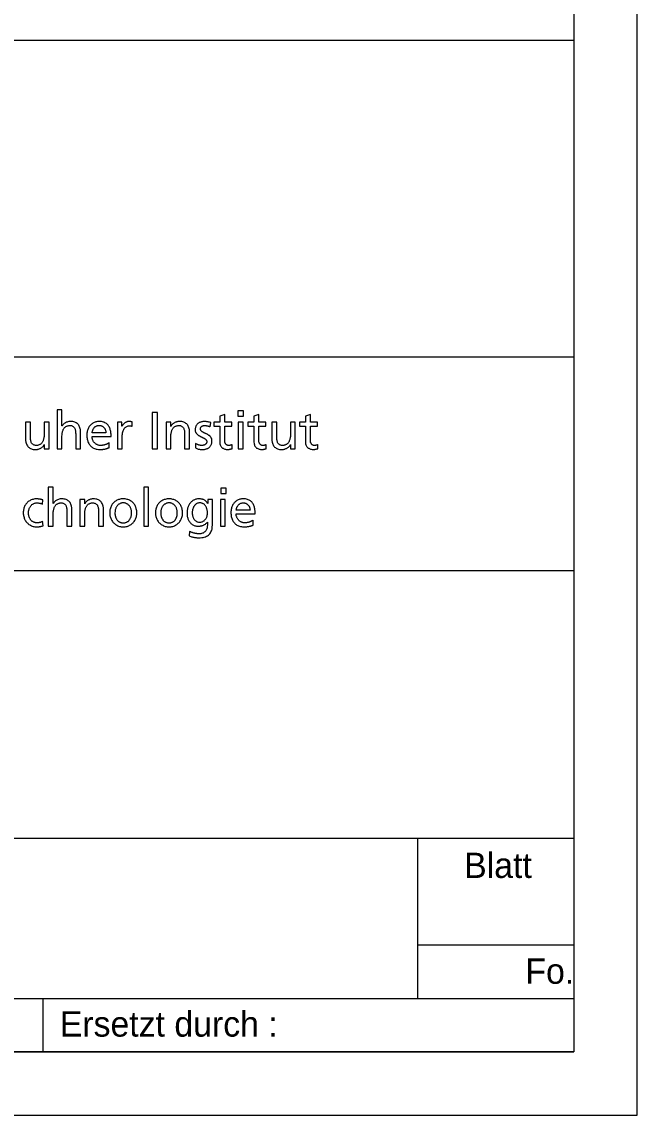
# Model space of a CAD drawing. Extents: x 0 to 168, y 0 to 119.
# Drawn here: x 158.47 to 168.2, y 0 to 17.3 of the extents above; entities that cross this region are included whole.
import ezdxf

# ---------------------------------------------------------------- set-up
doc = ezdxf.new("R2010")
doc.units = 0
doc.layers.add('90_Plankopf', color=7, linetype='Continuous')

msp = doc.modelspace()

# ---------------------------------------------------------------- linework, layer by layer
at = {"layer": '90_Plankopf'}
for p, q in [((167.2, 16.998), (131.624, 16.998)), ((167.2, 16.998), (167.2, 1)), ((131.624, 11.998), (167.2, 11.998)), ((131.624, 11.998), (167.2, 11.998)), ((167.2, 11.998), (167.2, 1)), ((160.211, 10.897), (160.211, 10.966)), ((161.446, 10.888), (161.453, 10.956)), ((159.794, 10.792), (159.577, 10.792)), ((159.577, 10.734), (159.877, 10.734)), ((159.845, 10.559), (159.845, 10.636)), ((161.214, 10.624), (161.21, 10.554)), ((161.792, 10.543), (161.792, 10.609)), ((162.333, 10.543), (162.333, 10.609)), ((163.149, 10.543), (163.149, 10.609)), ((158.79, 9.667), (158.797, 9.732)), ((162.075, 9.568), (161.857, 9.568)), ((158.8, 9.325), (158.794, 9.394)), ((161.857, 9.51), (162.157, 9.51)), ((162.125, 9.335), (162.125, 9.412)), ((161.119, 9.235), (161.111, 9.163)), ((150.4, 8.614), (167.2, 8.614)), ((150.4, 4.384), (167.2, 4.384)), ((164.729, 1.846), (164.729, 4.384)), ((164.729, 2.692), (167.2, 2.692)), ((150.4, 1.846), (167.2, 1.846)), ((158.8, 1), (158.8, 1.846)), ((167.2, 1), (131.624, 1)), ((133.96, 1), (167.2, 1)), ((133.96, 1), (167.2, 1))]:
    msp.add_line(p, q, dxfattribs=at)
for points in [[(0, 0), (168.2, 0), (168.2, 118.8), (0, 118.8)], [(5, 117.8), (167.2, 117.8), (167.2, 1), (5, 1)]]:
    msp.add_lwpolyline(points, close=True, dxfattribs=at)
for points in [[(159.102, 10.902), (159.1, 10.902), (159.1, 11.16), (159.023, 11.16), (159.023, 10.541), (159.1, 10.541), (159.1, 10.736)], [(160.529, 10.541), (160.612, 10.541), (160.612, 11.117), (160.529, 11.117), (160.529, 10.541)], [(161.674, 10.669), (161.674, 10.899), (161.786, 10.899), (161.786, 10.962), (161.674, 10.962), (161.674, 11.084), (161.597, 11.059), (161.597, 10.962), (161.502, 10.962), (161.502, 10.899), (161.597, 10.899), (161.597, 10.653)], [(161.971, 11.056), (161.971, 11.144), (161.883, 11.144), (161.883, 11.056), (161.971, 11.056)], [(162.215, 10.669), (162.215, 10.899), (162.327, 10.899), (162.327, 10.962), (162.215, 10.962), (162.215, 11.084), (162.138, 11.059), (162.138, 10.962), (162.043, 10.962), (162.043, 10.899), (162.138, 10.899), (162.138, 10.653)], [(163.031, 10.669), (163.031, 10.899), (163.142, 10.899), (163.142, 10.962), (163.031, 10.962), (163.031, 11.084), (162.953, 11.059), (162.953, 10.962), (162.858, 10.962), (162.858, 10.899), (162.953, 10.899), (162.953, 10.653)], [(158.601, 10.744), (158.601, 10.962), (158.523, 10.962), (158.523, 10.712)], [(158.819, 10.608), (158.82, 10.608), (158.82, 10.541), (158.895, 10.541), (158.895, 10.962), (158.818, 10.962), (158.818, 10.767)], [(160.05, 10.897), (160.049, 10.897), (160.049, 10.962), (159.976, 10.962), (159.976, 10.541), (160.054, 10.541), (160.054, 10.733)], [(160.823, 10.895), (160.822, 10.895), (160.822, 10.962), (160.746, 10.962), (160.746, 10.541), (160.824, 10.541), (160.824, 10.736)], [(161.888, 10.962), (161.888, 10.541), (161.966, 10.541), (161.966, 10.962), (161.888, 10.962)], [(162.497, 10.744), (162.497, 10.962), (162.419, 10.962), (162.419, 10.712)], [(162.715, 10.608), (162.716, 10.608), (162.716, 10.541), (162.791, 10.541), (162.791, 10.962), (162.714, 10.962), (162.714, 10.767)], [(159.317, 10.759), (159.317, 10.541), (159.395, 10.541), (159.395, 10.791)], [(161.041, 10.759), (161.041, 10.541), (161.119, 10.541), (161.119, 10.791)], [(158.964, 9.678), (158.962, 9.678), (158.962, 9.936), (158.884, 9.936), (158.884, 9.317), (158.962, 9.317), (158.962, 9.512)], [(160.393, 9.317), (160.47, 9.317), (160.47, 9.936), (160.393, 9.936), (160.393, 9.317)], [(161.699, 9.832), (161.699, 9.92), (161.611, 9.92), (161.611, 9.832), (161.699, 9.832)], [(159.461, 9.671), (159.459, 9.671), (159.459, 9.738), (159.384, 9.738), (159.384, 9.317), (159.461, 9.317), (159.461, 9.512)], [(161.479, 9.335), (161.479, 9.738), (161.407, 9.738), (161.407, 9.676), (161.406, 9.676)], [(161.606, 9.738), (161.606, 9.317), (161.684, 9.317), (161.684, 9.738), (161.606, 9.738)], [(159.179, 9.535), (159.179, 9.317), (159.257, 9.317), (159.257, 9.567)], [(159.679, 9.535), (159.679, 9.317), (159.756, 9.317), (159.756, 9.567)], [(161.4, 9.382), (161.401, 9.382), (161.401, 9.341)]]:
    msp.add_lwpolyline(points, dxfattribs=at)
for points in [[(159.1, 10.736), (159.1, 10.762), (159.103, 10.785), (159.108, 10.806), (159.113, 10.827), (159.121, 10.846), (159.131, 10.861), (159.142, 10.876), (159.155, 10.888), (159.171, 10.897), (159.187, 10.905), (159.206, 10.909), (159.228, 10.909), (159.251, 10.908), (159.268, 10.902), (159.281, 10.89), (159.295, 10.879), (159.304, 10.862), (159.309, 10.841), (159.315, 10.819), (159.317, 10.792), (159.317, 10.759)], [(159.395, 10.791), (159.395, 10.829), (159.389, 10.861), (159.378, 10.888), (159.367, 10.915), (159.35, 10.936), (159.327, 10.95), (159.303, 10.965), (159.274, 10.972), (159.237, 10.972), (159.208, 10.972), (159.181, 10.966), (159.158, 10.954), (159.135, 10.942), (159.116, 10.924), (159.102, 10.902)], [(159.877, 10.734), (159.877, 10.768), (159.874, 10.8), (159.868, 10.829), (159.861, 10.857), (159.851, 10.882), (159.837, 10.904), (159.822, 10.925), (159.803, 10.942), (159.78, 10.954), (159.756, 10.966), (159.726, 10.972), (159.691, 10.972), (159.661, 10.972), (159.635, 10.967), (159.61, 10.956), (159.586, 10.946), (159.565, 10.931), (159.548, 10.912), (159.531, 10.893), (159.517, 10.871), (159.508, 10.845), (159.499, 10.819), (159.494, 10.79), (159.494, 10.759), (159.494, 10.725), (159.498, 10.694), (159.507, 10.666), (159.516, 10.638), (159.529, 10.614), (159.547, 10.594), (159.565, 10.574), (159.587, 10.558), (159.615, 10.548), (159.642, 10.537), (159.675, 10.531), (159.712, 10.531), (159.735, 10.531), (159.754, 10.533), (159.771, 10.536), (159.787, 10.539), (159.801, 10.543), (159.813, 10.547), (159.824, 10.551), (159.835, 10.555), (159.845, 10.559)], [(159.577, 10.792), (159.578, 10.806), (159.581, 10.82), (159.586, 10.833), (159.591, 10.847), (159.598, 10.86), (159.607, 10.871), (159.616, 10.883), (159.627, 10.892), (159.641, 10.899), (159.654, 10.906), (159.671, 10.909), (159.69, 10.909), (159.706, 10.909), (159.721, 10.906), (159.734, 10.9), (159.747, 10.894), (159.758, 10.886), (159.767, 10.875), (159.776, 10.864), (159.783, 10.852), (159.787, 10.838), (159.792, 10.823), (159.794, 10.808), (159.794, 10.792)], [(160.211, 10.966), (160.206, 10.967), (160.201, 10.968), (160.196, 10.969), (160.191, 10.97), (160.186, 10.971), (160.18, 10.971), (160.174, 10.972), (160.168, 10.972), (160.16, 10.972), (160.145, 10.972), (160.131, 10.969), (160.116, 10.962), (160.102, 10.956), (160.09, 10.947), (160.078, 10.936), (160.067, 10.925), (160.057, 10.912), (160.05, 10.897)], [(160.054, 10.733), (160.054, 10.768), (160.059, 10.799), (160.068, 10.824), (160.078, 10.85), (160.091, 10.87), (160.108, 10.883), (160.125, 10.897), (160.145, 10.904), (160.168, 10.904), (160.175, 10.904), (160.182, 10.904), (160.19, 10.903), (160.197, 10.902), (160.204, 10.9), (160.211, 10.897)], [(161.119, 10.791), (161.119, 10.829), (161.113, 10.861), (161.102, 10.888), (161.091, 10.915), (161.074, 10.936), (161.05, 10.95), (161.027, 10.965), (160.997, 10.972), (160.961, 10.972), (160.941, 10.972), (160.922, 10.969), (160.904, 10.963), (160.886, 10.957), (160.87, 10.948), (160.856, 10.936), (160.842, 10.925), (160.831, 10.911), (160.823, 10.895)], [(160.824, 10.736), (160.824, 10.762), (160.826, 10.785), (160.832, 10.806), (160.837, 10.827), (160.844, 10.846), (160.855, 10.861), (160.865, 10.876), (160.879, 10.888), (160.895, 10.897), (160.911, 10.905), (160.93, 10.909), (160.952, 10.909), (160.974, 10.908), (160.992, 10.902), (161.005, 10.89), (161.018, 10.879), (161.027, 10.862), (161.033, 10.841), (161.039, 10.819), (161.041, 10.792), (161.041, 10.759)], [(161.453, 10.956), (161.438, 10.96), (161.422, 10.964), (161.407, 10.967), (161.391, 10.97), (161.374, 10.972), (161.356, 10.972), (161.336, 10.972), (161.316, 10.969), (161.298, 10.964), (161.28, 10.959), (161.264, 10.951), (161.251, 10.94), (161.237, 10.929), (161.227, 10.916), (161.219, 10.9), (161.212, 10.883), (161.208, 10.864), (161.208, 10.842), (161.208, 10.826), (161.211, 10.811), (161.218, 10.799), (161.225, 10.787), (161.233, 10.776), (161.244, 10.767), (161.255, 10.758), (161.267, 10.75), (161.28, 10.743), (161.293, 10.736), (161.306, 10.729), (161.319, 10.723), (161.331, 10.717), (161.343, 10.711), (161.354, 10.704), (161.365, 10.698), (161.374, 10.691), (161.38, 10.683), (161.387, 10.675), (161.39, 10.665), (161.39, 10.654), (161.39, 10.643), (161.388, 10.633), (161.383, 10.626), (161.378, 10.618), (161.372, 10.612), (161.364, 10.607), (161.356, 10.602), (161.348, 10.599), (161.338, 10.597), (161.329, 10.595), (161.32, 10.594), (161.311, 10.594), (161.303, 10.594), (161.294, 10.595), (161.283, 10.597), (161.272, 10.599), (161.26, 10.603), (161.248, 10.607), (161.236, 10.612), (161.225, 10.617), (161.214, 10.624)], [(161.21, 10.554), (161.228, 10.545), (161.247, 10.539), (161.267, 10.536), (161.286, 10.532), (161.306, 10.531), (161.326, 10.531), (161.345, 10.531), (161.363, 10.534), (161.38, 10.539), (161.398, 10.544), (161.414, 10.552), (161.428, 10.563), (161.441, 10.574), (161.452, 10.588), (161.46, 10.604), (161.469, 10.621), (161.473, 10.64), (161.473, 10.662), (161.473, 10.682), (161.469, 10.698), (161.463, 10.711), (161.456, 10.724), (161.447, 10.736), (161.437, 10.745), (161.426, 10.754), (161.414, 10.762), (161.401, 10.769), (161.388, 10.776), (161.375, 10.782), (161.362, 10.787), (161.349, 10.793), (161.337, 10.799), (161.327, 10.805), (161.316, 10.812), (161.307, 10.819), (161.3, 10.827), (161.294, 10.836), (161.291, 10.846), (161.29, 10.858), (161.291, 10.87), (161.294, 10.879), (161.301, 10.887), (161.308, 10.894), (161.317, 10.9), (161.328, 10.904), (161.339, 10.908), (161.351, 10.909), (161.365, 10.909), (161.369, 10.909), (161.375, 10.909), (161.383, 10.908), (161.39, 10.906), (161.398, 10.905), (161.406, 10.903), (161.414, 10.901), (161.422, 10.898), (161.429, 10.896), (161.436, 10.893), (161.442, 10.891), (161.446, 10.888)], [(158.818, 10.767), (158.818, 10.742), (158.815, 10.718), (158.81, 10.697), (158.805, 10.676), (158.798, 10.658), (158.787, 10.642), (158.777, 10.627), (158.763, 10.615), (158.747, 10.607), (158.731, 10.598), (158.712, 10.594), (158.69, 10.594), (158.668, 10.595), (158.65, 10.602), (158.637, 10.613), (158.624, 10.624), (158.614, 10.641), (158.609, 10.662), (158.603, 10.684), (158.601, 10.711), (158.601, 10.744)], [(159.845, 10.636), (159.84, 10.632), (159.833, 10.628), (159.824, 10.623), (159.815, 10.618), (159.804, 10.614), (159.792, 10.609), (159.78, 10.605), (159.768, 10.601), (159.754, 10.598), (159.741, 10.596), (159.728, 10.594), (159.715, 10.594), (159.697, 10.594), (159.679, 10.597), (159.663, 10.604), (159.646, 10.611), (159.631, 10.621), (159.618, 10.633), (159.605, 10.645), (159.595, 10.66), (159.588, 10.677), (159.581, 10.694), (159.577, 10.713), (159.577, 10.734)], [(162.714, 10.767), (162.714, 10.742), (162.711, 10.718), (162.706, 10.697), (162.701, 10.676), (162.693, 10.658), (162.683, 10.642), (162.672, 10.627), (162.659, 10.615), (162.643, 10.607), (162.627, 10.598), (162.608, 10.594), (162.586, 10.594), (162.563, 10.595), (162.546, 10.602), (162.533, 10.613), (162.519, 10.624), (162.51, 10.641), (162.505, 10.662), (162.499, 10.684), (162.497, 10.711), (162.497, 10.744)], [(158.523, 10.712), (158.523, 10.674), (158.529, 10.642), (158.54, 10.615), (158.551, 10.588), (158.568, 10.567), (158.592, 10.553), (158.615, 10.539), (158.645, 10.531), (158.681, 10.531), (158.701, 10.531), (158.72, 10.534), (158.738, 10.54), (158.756, 10.547), (158.772, 10.555), (158.786, 10.567), (158.8, 10.578), (158.811, 10.592), (158.819, 10.608)], [(161.597, 10.653), (161.597, 10.625), (161.602, 10.602), (161.613, 10.584), (161.623, 10.566), (161.638, 10.553), (161.657, 10.544), (161.677, 10.536), (161.699, 10.531), (161.726, 10.531), (161.739, 10.531), (161.751, 10.533), (161.762, 10.535), (161.773, 10.538), (161.784, 10.54), (161.792, 10.543)], [(161.792, 10.609), (161.787, 10.605), (161.779, 10.602), (161.771, 10.599), (161.762, 10.596), (161.751, 10.594), (161.74, 10.594), (161.728, 10.594), (161.717, 10.597), (161.707, 10.603), (161.697, 10.608), (161.689, 10.617), (161.683, 10.628), (161.677, 10.639), (161.674, 10.653), (161.674, 10.669)], [(162.138, 10.653), (162.138, 10.625), (162.143, 10.602), (162.153, 10.584), (162.164, 10.566), (162.179, 10.553), (162.198, 10.544), (162.217, 10.536), (162.24, 10.531), (162.267, 10.531), (162.28, 10.531), (162.292, 10.533), (162.303, 10.535), (162.314, 10.538), (162.324, 10.54), (162.333, 10.543)], [(162.333, 10.609), (162.327, 10.605), (162.32, 10.602), (162.311, 10.599), (162.303, 10.596), (162.292, 10.594), (162.28, 10.594), (162.268, 10.594), (162.257, 10.597), (162.248, 10.603), (162.238, 10.608), (162.23, 10.617), (162.224, 10.628), (162.218, 10.639), (162.215, 10.653), (162.215, 10.669)], [(162.419, 10.712), (162.419, 10.674), (162.425, 10.642), (162.436, 10.615), (162.447, 10.588), (162.464, 10.567), (162.487, 10.553), (162.511, 10.539), (162.54, 10.531), (162.577, 10.531), (162.596, 10.531), (162.615, 10.534), (162.633, 10.54), (162.651, 10.547), (162.667, 10.555), (162.682, 10.567), (162.696, 10.578), (162.707, 10.592), (162.715, 10.608)], [(162.953, 10.653), (162.953, 10.625), (162.959, 10.602), (162.969, 10.584), (162.979, 10.566), (162.994, 10.553), (163.014, 10.544), (163.033, 10.536), (163.056, 10.531), (163.083, 10.531), (163.095, 10.531), (163.107, 10.533), (163.118, 10.535), (163.13, 10.538), (163.14, 10.54), (163.149, 10.543)], [(163.149, 10.609), (163.143, 10.605), (163.136, 10.602), (163.127, 10.599), (163.118, 10.596), (163.108, 10.594), (163.096, 10.594), (163.084, 10.594), (163.073, 10.597), (163.063, 10.603), (163.053, 10.608), (163.046, 10.617), (163.04, 10.628), (163.034, 10.639), (163.031, 10.653), (163.031, 10.669)], [(158.797, 9.732), (158.789, 9.735), (158.78, 9.737), (158.77, 9.74), (158.759, 9.742), (158.748, 9.744), (158.736, 9.746), (158.724, 9.747), (158.713, 9.748), (158.703, 9.748), (158.67, 9.748), (158.641, 9.742), (158.615, 9.732), (158.589, 9.721), (158.566, 9.706), (158.547, 9.686), (158.528, 9.666), (158.514, 9.643), (158.504, 9.616), (158.493, 9.589), (158.488, 9.56), (158.488, 9.528), (158.488, 9.498), (158.494, 9.469), (158.504, 9.442), (158.514, 9.416), (158.529, 9.393), (158.548, 9.372), (158.567, 9.352), (158.589, 9.336), (158.616, 9.325), (158.642, 9.313), (158.671, 9.308), (158.703, 9.307), (158.712, 9.307), (158.722, 9.308), (158.733, 9.309), (158.744, 9.309), (158.755, 9.311), (158.767, 9.314), (158.778, 9.316), (158.789, 9.32), (158.8, 9.325)], [(158.794, 9.394), (158.786, 9.389), (158.777, 9.384), (158.768, 9.381), (158.759, 9.377), (158.749, 9.375), (158.739, 9.373), (158.729, 9.371), (158.72, 9.37), (158.711, 9.37), (158.691, 9.37), (158.673, 9.373), (158.658, 9.379), (158.643, 9.385), (158.63, 9.393), (158.618, 9.404), (158.607, 9.414), (158.598, 9.426), (158.591, 9.44), (158.584, 9.453), (158.579, 9.467), (158.576, 9.482), (158.572, 9.498), (158.571, 9.513), (158.571, 9.528), (158.571, 9.548), (158.574, 9.568), (158.58, 9.586), (158.586, 9.605), (158.594, 9.622), (158.606, 9.637), (158.617, 9.652), (158.631, 9.663), (158.648, 9.672), (158.665, 9.681), (158.684, 9.685), (158.706, 9.685), (158.719, 9.685), (158.732, 9.684), (158.746, 9.681), (158.761, 9.678), (158.775, 9.673), (158.79, 9.667)], [(158.962, 9.512), (158.962, 9.538), (158.965, 9.561), (158.97, 9.582), (158.975, 9.604), (158.982, 9.622), (158.993, 9.637), (159.003, 9.653), (159.017, 9.664), (159.033, 9.673), (159.049, 9.681), (159.068, 9.685), (159.09, 9.685), (159.112, 9.684), (159.13, 9.678), (159.143, 9.666), (159.156, 9.655), (159.165, 9.639), (159.171, 9.617), (159.177, 9.595), (159.179, 9.568), (159.179, 9.535)], [(159.257, 9.567), (159.257, 9.605), (159.251, 9.638), (159.24, 9.665), (159.229, 9.691), (159.212, 9.712), (159.188, 9.726), (159.165, 9.741), (159.135, 9.748), (159.099, 9.748), (159.069, 9.748), (159.043, 9.742), (159.02, 9.73), (158.997, 9.718), (158.978, 9.7), (158.964, 9.678)], [(159.756, 9.567), (159.756, 9.605), (159.751, 9.638), (159.739, 9.665), (159.728, 9.691), (159.711, 9.712), (159.688, 9.726), (159.665, 9.741), (159.635, 9.748), (159.598, 9.748), (159.579, 9.748), (159.56, 9.745), (159.542, 9.739), (159.524, 9.733), (159.508, 9.724), (159.494, 9.712), (159.48, 9.701), (159.468, 9.687), (159.461, 9.671)], [(159.461, 9.512), (159.461, 9.538), (159.464, 9.561), (159.469, 9.582), (159.474, 9.604), (159.482, 9.622), (159.492, 9.637), (159.503, 9.653), (159.516, 9.664), (159.532, 9.673), (159.548, 9.681), (159.567, 9.685), (159.589, 9.685), (159.612, 9.684), (159.63, 9.678), (159.643, 9.666), (159.656, 9.655), (159.665, 9.639), (159.67, 9.617), (159.676, 9.595), (159.679, 9.568), (159.679, 9.535)], [(160.279, 9.578), (160.276, 9.591), (160.273, 9.604), (160.268, 9.616), (160.258, 9.643), (160.244, 9.666), (160.225, 9.686), (160.206, 9.706), (160.183, 9.721), (160.157, 9.732), (160.131, 9.742), (160.102, 9.748), (160.07, 9.748), (160.038, 9.748), (160.008, 9.742), (159.982, 9.732), (159.956, 9.721), (159.933, 9.706), (159.914, 9.686), (159.895, 9.666), (159.881, 9.643), (159.871, 9.616), (159.86, 9.589), (159.855, 9.56), (159.855, 9.528)], [(159.938, 9.528), (159.938, 9.548), (159.941, 9.568), (159.947, 9.586), (159.953, 9.605), (159.961, 9.622), (159.973, 9.637), (159.984, 9.652), (159.998, 9.663), (160.014, 9.672), (160.03, 9.681), (160.049, 9.685), (160.07, 9.685), (160.09, 9.685), (160.109, 9.681), (160.125, 9.672), (160.141, 9.663), (160.155, 9.652), (160.166, 9.637), (160.178, 9.622), (160.186, 9.605), (160.192, 9.586), (160.198, 9.568), (160.201, 9.548), (160.201, 9.528), (160.201, 9.513), (160.199, 9.498), (160.196, 9.482), (160.193, 9.467), (160.188, 9.453), (160.181, 9.44), (160.174, 9.426), (160.166, 9.414), (160.155, 9.404), (160.145, 9.393), (160.133, 9.385), (160.118, 9.379), (160.104, 9.373), (160.088, 9.37), (160.07, 9.37), (160.052, 9.37), (160.035, 9.373), (160.021, 9.379), (160.007, 9.385), (159.994, 9.393), (159.984, 9.404), (159.973, 9.414), (159.965, 9.426), (159.958, 9.44), (159.951, 9.453), (159.946, 9.467), (159.943, 9.482), (159.939, 9.498), (159.938, 9.513), (159.938, 9.528)], [(161.003, 9.578), (161, 9.591), (160.997, 9.604), (160.992, 9.616), (160.982, 9.643), (160.968, 9.666), (160.949, 9.686), (160.93, 9.706), (160.907, 9.721), (160.881, 9.732), (160.855, 9.742), (160.826, 9.748), (160.794, 9.748), (160.762, 9.748), (160.732, 9.742), (160.706, 9.732), (160.68, 9.721), (160.657, 9.706), (160.638, 9.686), (160.619, 9.666), (160.605, 9.643), (160.595, 9.616), (160.585, 9.589), (160.579, 9.56), (160.579, 9.528)], [(160.662, 9.528), (160.662, 9.548), (160.665, 9.568), (160.671, 9.586), (160.677, 9.605), (160.685, 9.622), (160.697, 9.637), (160.708, 9.652), (160.722, 9.663), (160.738, 9.672), (160.754, 9.681), (160.773, 9.685), (160.794, 9.685), (160.815, 9.685), (160.833, 9.681), (160.849, 9.672), (160.865, 9.663), (160.879, 9.652), (160.89, 9.637), (160.902, 9.622), (160.91, 9.605), (160.916, 9.586), (160.922, 9.568), (160.925, 9.548), (160.925, 9.528), (160.925, 9.513), (160.923, 9.498), (160.92, 9.482), (160.917, 9.467), (160.912, 9.453), (160.905, 9.44), (160.898, 9.426), (160.89, 9.414), (160.879, 9.404), (160.869, 9.393), (160.857, 9.385), (160.842, 9.379), (160.828, 9.373), (160.812, 9.37), (160.794, 9.37), (160.776, 9.37), (160.759, 9.373), (160.745, 9.379), (160.731, 9.385), (160.718, 9.393), (160.708, 9.404), (160.697, 9.414), (160.689, 9.426), (160.682, 9.44), (160.675, 9.453), (160.67, 9.467), (160.667, 9.482), (160.663, 9.498), (160.662, 9.513), (160.662, 9.528)], [(161.406, 9.676), (161.398, 9.691), (161.388, 9.704), (161.376, 9.715), (161.364, 9.725), (161.349, 9.734), (161.331, 9.739), (161.313, 9.745), (161.291, 9.748), (161.267, 9.748), (161.241, 9.748), (161.219, 9.744), (161.199, 9.735), (161.178, 9.727), (161.161, 9.715), (161.146, 9.7), (161.131, 9.686), (161.118, 9.669), (161.108, 9.65), (161.098, 9.631), (161.091, 9.611), (161.086, 9.589), (161.081, 9.568), (161.079, 9.546), (161.079, 9.524), (161.079, 9.497), (161.082, 9.471), (161.09, 9.446), (161.097, 9.421), (161.109, 9.399), (161.124, 9.38), (161.138, 9.361), (161.157, 9.345), (161.18, 9.334), (161.202, 9.323), (161.229, 9.318), (161.259, 9.317), (161.277, 9.317), (161.294, 9.32), (161.312, 9.324), (161.329, 9.329), (161.345, 9.337), (161.36, 9.346), (161.376, 9.356), (161.389, 9.368), (161.4, 9.382)], [(161.278, 9.38), (161.26, 9.38), (161.244, 9.384), (161.23, 9.392), (161.215, 9.4), (161.203, 9.411), (161.193, 9.425), (161.182, 9.438), (161.175, 9.454), (161.169, 9.472), (161.164, 9.49), (161.161, 9.509), (161.161, 9.529), (161.161, 9.543), (161.163, 9.558), (161.166, 9.572), (161.169, 9.587), (161.174, 9.601), (161.18, 9.615), (161.186, 9.628), (161.194, 9.64), (161.203, 9.651), (161.213, 9.661), (161.224, 9.67), (161.236, 9.676), (161.249, 9.682), (161.263, 9.685), (161.278, 9.685), (161.299, 9.685), (161.317, 9.681), (161.333, 9.672), (161.348, 9.664), (161.361, 9.652), (161.371, 9.637), (161.381, 9.622), (161.389, 9.605), (161.394, 9.585), (161.399, 9.566), (161.401, 9.545), (161.401, 9.523), (161.401, 9.503), (161.398, 9.485), (161.393, 9.467), (161.387, 9.45), (161.378, 9.435), (161.367, 9.422), (161.356, 9.409), (161.343, 9.399), (161.328, 9.391), (161.313, 9.384), (161.297, 9.38), (161.278, 9.38)], [(162.157, 9.51), (162.157, 9.544), (162.154, 9.576), (162.148, 9.605), (162.142, 9.634), (162.131, 9.659), (162.117, 9.68), (162.102, 9.701), (162.083, 9.718), (162.06, 9.73), (162.036, 9.742), (162.006, 9.748), (161.971, 9.748), (161.942, 9.748), (161.915, 9.743), (161.89, 9.732), (161.866, 9.722), (161.845, 9.707), (161.828, 9.688), (161.811, 9.669), (161.797, 9.647), (161.788, 9.621), (161.779, 9.595), (161.774, 9.567), (161.774, 9.535), (161.774, 9.501), (161.778, 9.47), (161.787, 9.442), (161.796, 9.414), (161.809, 9.39), (161.827, 9.37), (161.845, 9.35), (161.868, 9.334), (161.895, 9.324), (161.922, 9.313), (161.955, 9.308), (161.992, 9.307), (162.015, 9.308), (162.034, 9.309), (162.051, 9.312), (162.067, 9.315), (162.081, 9.319), (162.093, 9.323), (162.104, 9.327), (162.115, 9.331), (162.125, 9.335)], [(161.857, 9.568), (161.858, 9.582), (161.861, 9.596), (161.866, 9.609), (161.871, 9.623), (161.878, 9.636), (161.887, 9.647), (161.896, 9.659), (161.907, 9.668), (161.921, 9.675), (161.934, 9.682), (161.951, 9.685), (161.97, 9.685), (161.986, 9.685), (162.001, 9.682), (162.014, 9.676), (162.027, 9.67), (162.038, 9.662), (162.047, 9.651), (162.056, 9.64), (162.063, 9.628), (162.068, 9.614), (162.072, 9.6), (162.075, 9.584), (162.075, 9.568)], [(159.855, 9.528), (159.855, 9.498), (159.861, 9.469), (159.871, 9.442), (159.881, 9.416), (159.896, 9.393), (159.915, 9.372), (159.934, 9.352), (159.956, 9.336), (159.983, 9.325), (160.009, 9.313), (160.038, 9.308), (160.07, 9.307), (160.101, 9.308), (160.131, 9.313), (160.156, 9.325), (160.183, 9.336), (160.205, 9.352), (160.224, 9.372), (160.243, 9.393), (160.258, 9.416), (160.268, 9.442), (160.278, 9.469), (160.283, 9.498), (160.284, 9.528), (160.284, 9.545), (160.282, 9.562), (160.279, 9.578)], [(160.579, 9.528), (160.579, 9.498), (160.585, 9.469), (160.595, 9.442), (160.605, 9.416), (160.62, 9.393), (160.639, 9.372), (160.658, 9.352), (160.681, 9.336), (160.707, 9.325), (160.733, 9.313), (160.762, 9.308), (160.794, 9.307), (160.826, 9.308), (160.855, 9.313), (160.881, 9.325), (160.907, 9.336), (160.929, 9.352), (160.948, 9.372), (160.967, 9.393), (160.982, 9.416), (160.992, 9.442), (161.002, 9.469), (161.007, 9.498), (161.008, 9.528), (161.008, 9.545), (161.006, 9.562), (161.003, 9.578)], [(161.401, 9.341), (161.401, 9.311), (161.396, 9.286), (161.386, 9.264), (161.375, 9.243), (161.361, 9.226), (161.341, 9.214), (161.322, 9.203), (161.298, 9.197), (161.271, 9.197), (161.257, 9.197), (161.244, 9.197), (161.232, 9.199), (161.219, 9.2), (161.208, 9.203), (161.196, 9.206), (161.184, 9.209), (161.172, 9.212), (161.16, 9.217), (161.147, 9.222), (161.134, 9.228), (161.119, 9.235)], [(162.125, 9.412), (162.12, 9.408), (162.113, 9.404), (162.104, 9.399), (162.095, 9.394), (162.084, 9.39), (162.072, 9.385), (162.06, 9.381), (162.048, 9.377), (162.034, 9.374), (162.021, 9.372), (162.008, 9.37), (161.995, 9.37), (161.977, 9.37), (161.959, 9.374), (161.943, 9.38), (161.926, 9.387), (161.911, 9.397), (161.898, 9.409), (161.886, 9.421), (161.875, 9.436), (161.868, 9.453), (161.861, 9.471), (161.857, 9.49), (161.857, 9.51)], [(161.111, 9.163), (161.133, 9.155), (161.153, 9.149), (161.17, 9.145), (161.187, 9.141), (161.203, 9.138), (161.218, 9.136), (161.233, 9.135), (161.247, 9.134), (161.262, 9.134), (161.312, 9.134), (161.353, 9.142), (161.385, 9.158), (161.417, 9.174), (161.441, 9.196), (161.456, 9.226), (161.472, 9.256), (161.479, 9.293), (161.479, 9.335)]]:
    msp.add_open_spline(points, degree=3, dxfattribs=at)

# ---------------------------------------------------------------- texts
for s, p in [('Blatt', (165.463, 3.752)), ('Fo.', (166.432, 2.078)), ('Ersetzt durch :', (159.065, 1.242))]:
    msp.add_text(s, height=0.4, dxfattribs=at).set_placement(p)

doc.saveas('drawing.dxf')
